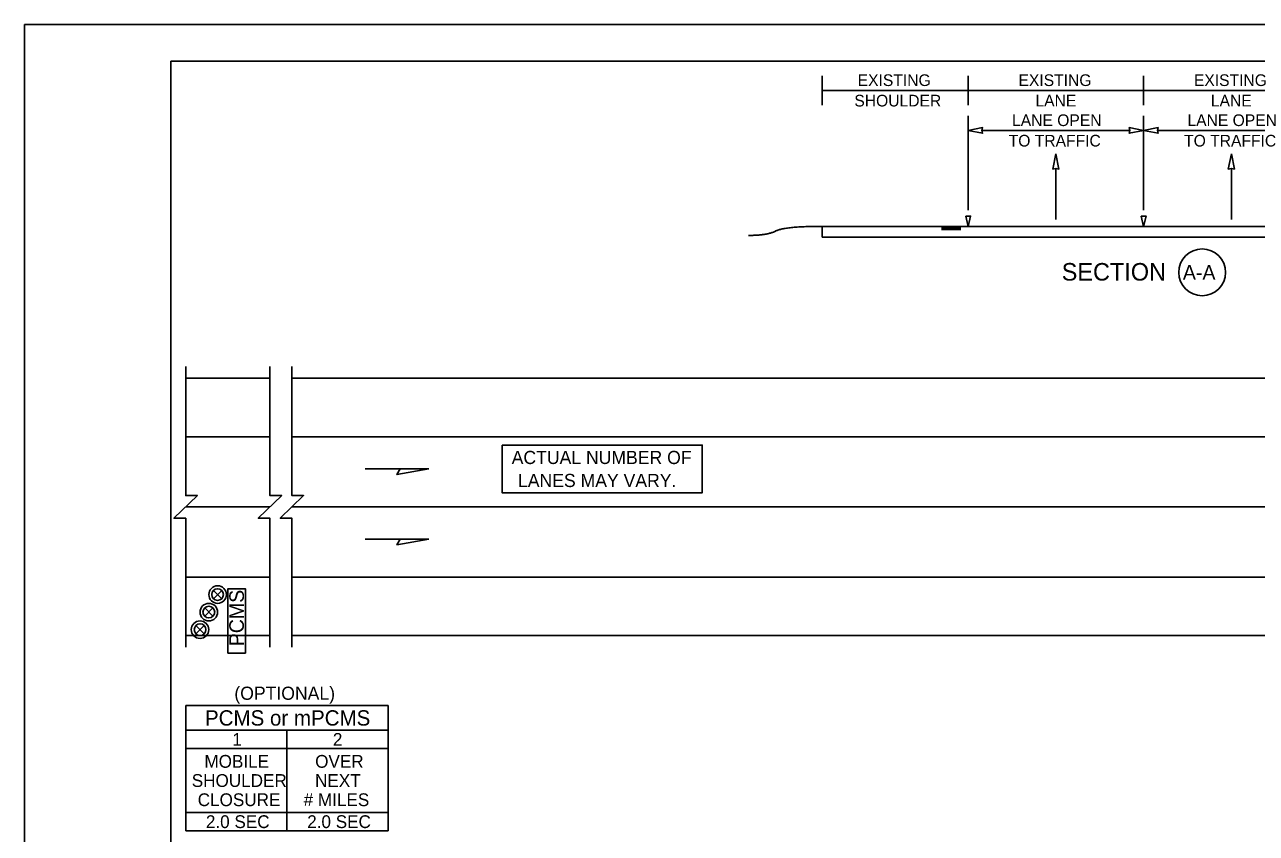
# Model space of a CAD drawing. Extents: x 0 to 17, y 0 to 11.
# Drawn here: x 0 to 8.43, y 5.47 to 11 of the extents above; entities that cross this region are included whole.
import ezdxf

# ---------------------------------------------------------------- set-up
doc = ezdxf.new("R2010")
doc.units = 0
for name, color, linetype in [('RD_ED_ShoulderPavedEdge', 7, 'Continuous'), ('RD_MK_LineEdgeWhite', 7, 'Continuous'), ('RD_MK_LineEdgeYellow', 7, 'Continuous'), ('RD_MK_LineLane', 7, 'Continuous'), ('SH_GI_PlotLimits', 7, 'Continuous'), ('SH_GI_SheetBorder3', 7, 'Continuous'), ('SH_TI_Tables', 7, 'Continuous'), ('SH_TI_WZSectionCut', 7, 'Continuous'), ('TR_WZ_ArrowLeftStrRightTurn', 7, 'Continuous'), ('TR_WZ_PCMS', 7, 'Continuous'), ('TR_WZ_PortableChangeMessageSign', 7, 'Continuous'), ('TR_WZ_TrafficSafetyDrum', 7, 'Continuous'), ('TR_WZ_WorkZoneDetails', 7, 'Continuous')]:
    doc.layers.add(name, color=color, linetype=linetype)

msp = doc.modelspace()

# ---------------------------------------------------------------- linework, layer by layer
at = {"layer": 'RD_ED_ShoulderPavedEdge'}
for p, q in [((1.1016, 8.5807), (1.6783, 8.5807)), ((1.8283, 8.5807), (16.62, 8.5807)), ((1.1016, 6.8207), (1.6783, 6.8207)), ((1.8283, 6.8207), (16.62, 6.8207))]:
    msp.add_line(p, q, dxfattribs=at)
at = {"layer": 'RD_MK_LineEdgeWhite'}
for p, q in [((1.1016, 7.2207), (1.6783, 7.2207)), ((1.8283, 7.2207), (16.62, 7.2207))]:
    msp.add_line(p, q, dxfattribs=at)
at = {"layer": 'RD_MK_LineEdgeYellow'}
for p, q in [((1.1016, 8.1807), (1.6783, 8.1807)), ((1.8283, 8.1807), (16.62, 8.1807))]:
    msp.add_line(p, q, dxfattribs=at)
at = {"layer": 'RD_MK_LineLane'}
for p, q in [((1.6783, 7.7007), (1.1016, 7.7007)), ((16.62, 7.7007), (1.8283, 7.7007))]:
    msp.add_line(p, q, dxfattribs=at)
at = {"layer": 'SH_GI_PlotLimits'}
msp.add_lwpolyline([(0, 11), (17, 11), (17, 0), (0, 0)], close=True, dxfattribs=at)
at = {"layer": 'SH_GI_SheetBorder3'}
for q in [(16.75, 10.75), (1, 0.25)]:
    msp.add_line((1, 10.75), q, dxfattribs=at)
at = {"layer": 'SH_TI_Tables'}
msp.add_lwpolyline([(3.266, 8.1232), (4.6358, 8.1232), (4.6358, 7.7968), (3.266, 7.7968)], close=True, dxfattribs=at)
at = {"layer": 'SH_TI_WZSectionCut'}
for p, q in [((5.4546, 10.45), (5.4546, 10.65)), ((6.4546, 10.45), (6.4546, 10.65)), ((7.6546, 10.45), (7.6546, 10.65)), ((5.4546, 10.55), (6.4546, 10.55)), ((6.4546, 10.55), (7.6546, 10.55)), ((7.6546, 10.55), (8.8546, 10.55)), ((6.4546, 9.7297), (6.4546, 10.376)), ((7.6546, 9.7297), (7.6546, 10.376)), ((7.5609, 10.276), (6.5484, 10.276)), ((8.7609, 10.276), (7.7484, 10.276)), ((5.4546, 9.6199), (5.4546, 9.5449)), ((9.8546, 9.6199), (5.4546, 9.6199)), ((6.2716, 9.6147), (6.4046, 9.6147)), ((6.2716, 9.6091), (6.4046, 9.6091)), ((9.8546, 9.5449), (5.4546, 9.5449)), ((6.2716, 9.6034), (6.4046, 9.6034)), ((6.2716, 9.5982), (6.4046, 9.5982))]:
    msp.add_line(p, q, dxfattribs=at)
for points in [[(6.4546, 10.276), (6.5529, 10.2567), (6.5484, 10.276), (6.5529, 10.2953)], [(7.6546, 10.276), (7.5564, 10.2567), (7.5609, 10.276), (7.5564, 10.2953)], [(7.6546, 10.276), (7.7529, 10.2567), (7.7484, 10.276), (7.7529, 10.2953)], [(6.4379, 9.6897), (6.4713, 9.6897), (6.4546, 9.6199)], [(7.638, 9.6897), (7.6713, 9.6897), (7.6547, 9.6199)]]:
    msp.add_lwpolyline(points, close=True, dxfattribs=at)
msp.add_circle((8.055, 9.305), 0.16, dxfattribs=at)
msp.add_open_spline([(5.4546, 9.6199), (5.2035, 9.6199), (5.078, 9.5578), (4.9525, 9.5578)], degree=2, dxfattribs=at)
at = {"layer": 'TR_WZ_ArrowLeftStrRightTurn'}
for p, q in [((7.0546, 10.0168), (7.0546, 9.667)), ((8.2546, 10.0168), (8.2546, 9.667))]:
    msp.add_line(p, q, dxfattribs=at)
for points in [[(7.0546, 10.117), (7.0752, 10.0119), (7.0546, 10.0168), (7.034, 10.0119)], [(8.2546, 10.117), (8.2752, 10.0119), (8.2546, 10.0168), (8.234, 10.0119)]]:
    msp.add_lwpolyline(points, close=True, dxfattribs=at)
at = {"layer": 'TR_WZ_PCMS'}
for points in [[(1.39, 7.1407), (1.51, 7.1407), (1.51, 6.7007), (1.39, 6.7007), (1.39, 7.1407)], [(1.39, 6.7007), (1.51, 6.7007), (1.51, 7.1407), (1.39, 7.1407), (1.39, 6.7007)]]:
    msp.add_lwpolyline(points, dxfattribs=at)
at = {"layer": 'TR_WZ_PortableChangeMessageSign'}
for p, q in [((1.1016, 6.3407), (2.4876, 6.3407)), ((1.1016, 5.4839), (1.1016, 6.3407)), ((2.4876, 5.4839), (2.4876, 6.3407)), ((2.4876, 6.1727), (1.1016, 6.1727)), ((1.7946, 5.4839), (1.7946, 6.1727)), ((1.7946, 6.0467), (1.1016, 6.0467)), ((2.4876, 6.0467), (1.7946, 6.0467)), ((1.1016, 5.6099), (1.7946, 5.6099)), ((1.7946, 5.6099), (2.4876, 5.6099)), ((2.4876, 5.4839), (1.1016, 5.4839))]:
    msp.add_line(p, q, dxfattribs=at)
at = {"layer": 'TR_WZ_TrafficSafetyDrum'}
for p, q in [((1.2917, 7.129), (1.3483, 7.0724)), ((1.3483, 7.129), (1.2917, 7.0724)), ((1.2317, 7.009), (1.2883, 6.9524)), ((1.2883, 7.009), (1.2317, 6.9524)), ((1.1717, 6.889), (1.2283, 6.8324)), ((1.2283, 6.889), (1.1717, 6.8324))]:
    msp.add_line(p, q, dxfattribs=at)
for centre, radius in [((1.32, 7.1007), 0.06), ((1.32, 7.1007), 0.06), ((1.32, 7.1007), 0.04), ((1.26, 6.9807), 0.06), ((1.26, 6.9807), 0.06), ((1.26, 6.9807), 0.04), ((1.2, 6.8607), 0.06), ((1.2, 6.8607), 0.06), ((1.2, 6.8607), 0.04)]:
    msp.add_circle(centre, radius, dxfattribs=at)
at = {"layer": 'TR_WZ_WorkZoneDetails'}
for p, q in [((2.5694, 7.96), (2.3283, 7.96)), ((2.5694, 7.48), (2.3283, 7.48))]:
    msp.add_line(p, q, dxfattribs=at)
for points in [[(1.1016, 6.7407), (1.1016, 7.6233), (1.0216, 7.6233), (1.1817, 7.7782), (1.1016, 7.7782), (1.1016, 8.6607)], [(1.6783, 6.7407), (1.6783, 7.6233), (1.5983, 7.6233), (1.7583, 7.7782), (1.6783, 7.7782), (1.6783, 8.6607)], [(1.8283, 6.7407), (1.8283, 7.6233), (1.7483, 7.6233), (1.9083, 7.7782), (1.8283, 7.7782), (1.8283, 8.6607)]]:
    msp.add_lwpolyline(points, dxfattribs=at)
for points in [[(2.766, 7.96), (2.5471, 7.9214), (2.5694, 7.96)], [(2.766, 7.48), (2.5471, 7.4414), (2.5694, 7.48)]]:
    msp.add_lwpolyline(points, close=True, dxfattribs=at)

# ---------------------------------------------------------------- texts
at = {"layer": 'SH_TI_Tables'}
for s, p in [('ACTUAL NUMBER OF', (3.3317, 7.9938)), ('LANES MAY VARY.', (3.375, 7.8363))]:
    msp.add_text(s, height=0.09, rotation=360, dxfattribs=at).set_placement(p)
at = {"layer": 'SH_TI_WZSectionCut'}
for s, height, p in [('EXISTING', 0.08, (5.6986, 10.58)), ('EXISTING', 0.08, (6.7986, 10.58)), ('EXISTING', 0.08, (7.9986, 10.58)), ('SHOULDER', 0.08, (5.6757, 10.44)), ('LANE', 0.08, (6.9145, 10.44)), ('LANE', 0.08, (8.1145, 10.44)), ('SECTION', 0.12, (7.0943, 9.2489)), ('A-A', 0.1, (7.9231, 9.255))]:
    msp.add_text(s, height=height, rotation=360, dxfattribs=at).set_placement(p)
for s, p in [('LANE OPEN', (6.7543, 10.306)), ('LANE OPEN', (7.9543, 10.306)), ('TO TRAFFIC', (6.7315, 10.166)), ('TO TRAFFIC', (7.9315, 10.166))]:
    msp.add_text(s, height=0.08, dxfattribs=at).set_placement(p)
at = {"layer": 'TR_WZ_PCMS'}
msp.add_text('PCMS', height=0.1, rotation=90, dxfattribs=at).set_placement((1.5, 6.7471))
at = {"layer": 'TR_WZ_PortableChangeMessageSign'}
for s, height, p in [('PCMS or mPCMS', 0.105, (1.2335, 6.2042)), ('1', 0.0875, (1.4208, 6.066)), ('2', 0.0875, (2.1087, 6.066)), ('MOBILE', 0.0875, (1.2299, 5.9158)), ('OVER', 0.0875, (1.9874, 5.9158)), ('SHOULDER', 0.0875, (1.1431, 5.7846)), ('NEXT', 0.0875, (1.9866, 5.7846)), ('CLOSURE', 0.0875, (1.184, 5.6533)), ('# MILES', 0.0875, (1.9088, 5.6533)), ('2.0 SEC', 0.0875, (1.2399, 5.5032)), ('2.0 SEC', 0.0875, (1.9329, 5.5032))]:
    msp.add_text(s, height=height, rotation=360, dxfattribs=at).set_placement(p)
at = {"layer": 'TR_WZ_WorkZoneDetails'}
msp.add_text('(OPTIONAL)', height=0.09, dxfattribs=at).set_placement((1.4346, 6.3807))

doc.saveas('drawing.dxf')
